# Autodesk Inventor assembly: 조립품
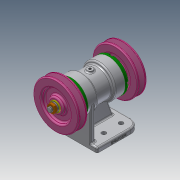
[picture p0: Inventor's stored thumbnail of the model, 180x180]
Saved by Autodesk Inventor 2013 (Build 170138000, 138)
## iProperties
Created: 2020-06
Part Number: 조립품
Document SubType Name: Assembly
Designer: CADCOM
Author: CADCOM
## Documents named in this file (12)
- C:\Users\CADCOM\Desktop\700606V1037\조립품.iam
- C:\Users\CADCOM\Desktop\700606V1037\본체부품.ipt
- C:\Users\CADCOM\Desktop\700606V1037\Ű 5x5x12.ipt
- C:\Users\CADCOM\Desktop\700606V1037\V-벨트풀리.ipt
- C:\Users\CADCOM\Desktop\700606V1037\너트 M10.ipt
- C:\Users\CADCOM\Desktop\700606V1037\베어링 6204.ipt
- C:\Users\CADCOM\Desktop\700606V1037\볼트 M4.ipt
- C:\Users\CADCOM\Desktop\700606V1037\스프링 와셔 10.ipt
- C:\Users\CADCOM\Desktop\700606V1037\오일 실 20 32 5.ipt
- C:\Users\CADCOM\Desktop\700606V1037\축.ipt
- C:\Users\CADCOM\Desktop\700606V1037\커버.ipt
- C:\Users\CADCOM\Desktop\700606V1037\평면 와셔 10x21.ipt
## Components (4 placed, 2 different names)
1. V-벨트풀리:1
2. Ű 5x5x12:2
3. Ű 5x5x12:3
4. V-벨트풀리:2
